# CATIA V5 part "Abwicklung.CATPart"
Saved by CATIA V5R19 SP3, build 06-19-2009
Part number: Part1
Bounding box of the stored display mesh (mm): x -1830 to 300, y -1300 to 50, z 0 to 970
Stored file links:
  C:\Tebisdaten\Abwicklung.CATPart
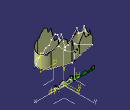
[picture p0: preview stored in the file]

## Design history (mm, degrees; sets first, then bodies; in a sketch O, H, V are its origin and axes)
AxisSystem1: origin (0, 0, 0), X (1, 0, 0), Y (0, 1, 0), Z (0, 0, 1)
Set1 "Geometrical Set.Def 1"
  Plane1: type Offset, RefPlane xy-plane, Offset 20
  Sketch1 on Plane1, origin (0, 0, 20), H (1, 0, 0), V (0, 1, 0)
    line L1 (-300, 50) -> (300, 50)
    line L2 (300, 50) -> (300, -50)
    line L3 (300, -50) -> (-300, -50)
    line L4 (-300, -50) -> (-300, 50)
    horizontal: L1 H, L3 H
    vertical: L2 V, L4 V
  Sketch2 on zx-plane, origin (0, 0, 0), H (-1, 0, 0), V (0, 0, 1)
    spline S1 through (-300, 140) (-200, 60) (-100, 100) (0, 140) (100, 60) (200, 100) (300, 150)
  Point1 "Start": (0, 0, 0), relative to vertex [element of Sketch1 | element of Sketch1], in AxisSystem1
  Extract1 "Extract.Richtung": ExtractElem Sketch1.L1
  Extract2 "Extract.Trennung": ExtractElem edge [face of Extrude1 from Sketch1.L2 | face of Extrude1 from Sketch1.L1]
Set2 "Flächen"
  Extrude1: Lim1 162, Lim2 0, Direction Plane1, Element1 Sketch1
  Extrude2: Lim1 162, Lim2 110, Direction zx-plane, Element1 Sketch2
  Split1 "Split.= Abzuwickelnde Fläche": ToCut Extrude1, Cutting Extrude2
Set3 "Abwicklung - Geoset zum Einsetzen von Selektion..."
  Unfold1: SpecsToUnfold Split1, Origin Point1, ReferenceDirection Extract1, SpecsToTear Extract2, AxisFirstDirection (0, 0, 1)
Set4 "Def 2"
  Plane2: type Offset, RefPlane xy-plane, Offset 100
  Sketch3 on Plane2, origin (0, 0, 100), H (1, 0, 0), V (0, 1, 0)
    line L1 (-1200, -600) -> (-800, -500)
    line L2 (-800, -500) -> (-200, -700)
    arc A1 centre (-297.3684, -992.1053) radius 307.906 from (-200, -700) to (-300, -1300) cw
    line L3 (-300, -1300) -> (-1080, -1293.3333)
    line L4 (-1080, -1293.3333) -> (-1080, -1040)
    arc A2 centre (-1275.5128, -1040) radius 195.5128 from (-1080, -1040) to (-1470, -1060) ccw
    line L5 (-1470, -1060) -> (-1780, -700)
    line L6 (-1780, -700) -> (-1200, -600)
    tangency: A1 L2, L3 A1, A2 L4
    vertical: L4 V
  Plane3: type Offset, RefPlane zx-plane, Offset 893, reversed
  Sketch4 on Plane3, origin (0, -893, 0), H (-1, 0, 0), V (0, 0, 1)
    line L1 (-240, 240) -> (20, 600)
    line L2 (20, 600) -> (100, 560)
    line L3 (100, 560) -> (190, 685)
    line L4 (190, 685) -> (320, 710)
    line L5 (320, 710) -> (413.8889, 840)
    line L6 (413.8889, 840) -> (550, 970)
    line L7 (550, 970) -> (650, 900)
    line L8 (650, 900) -> (690, 740)
    line L9 (690, 740) -> (794.1667, 840)
    line L10 (794.1667, 840) -> (862.8, 560)
    line L11 (862.8, 560) -> (930, 360)
    line L12 (930, 360) -> (1054.8, 360)
    line L13 (1054.8, 360) -> (1232.3, 583.1879)
    point P14 (1232.3, 583.1879)
    line L14 (1232.3, 583.1879) -> (1386.6861, 753.0126)
    line L15 (1386.6861, 753.0126) -> (1450, 540)
    line L16 (1450, 540) -> (1583.8317, 513.4502)
    line L17 (1583.8317, 513.4502) -> (1650.5455, 685)
    line L18 (1650.5455, 685) -> (1698.1548, 490.7704)
    point P19 (1698.1548, 490.7704)
    line L19 (1698.1548, 490.7704) -> (1830, 330)
    parallelism: L5 L1
    horizontal: L12 H
    coincidence: L16 P14, P19 L16
Set5 "Flächen-Radtour"
  Extrude3: Lim1 900, Lim2 0, Direction Plane2, Element1 Sketch3
  Extrude4: Lim1 503, Lim2 525, Direction Plane3, Element1 Sketch4
  Split2 "Split. = Abzuwickelndes Bergprofil": ToCut Extrude3, Cutting Extrude4
  Point2 "Start der Tour": (0, 0, 0), relative to vertex [face of Extrude3 from Sketch3.L1], in AxisSystem1
  Extract3 "Richtung": ExtractElem edge of Split2
  Line1 "Line. Start / Ziel Trennung": type Angle, LineSecondUpto Sketch3, RefPoint Point2, Curve Extract3, Support Split2, Start 0, End 20, Angle 90
Body1 (main body)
